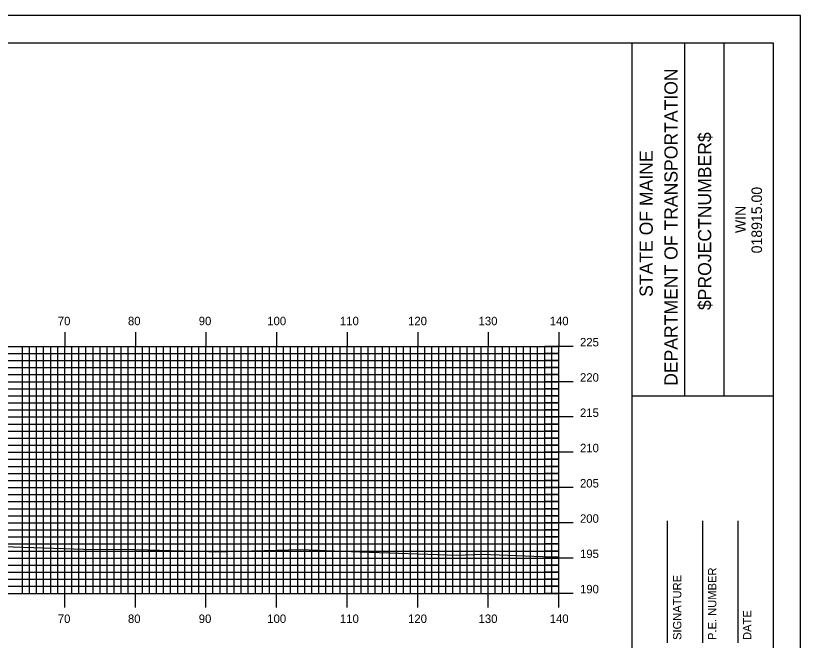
# Model space of a CAD drawing. Extents: x 1811374 to 1811717, y 442591 to 442811.
# Drawn here: x 1811602.4 to 1811713.6, y 442722 to 442810.5 of the extents above; entities that cross this region are included whole.
import ezdxf

# ---------------------------------------------------------------- set-up
doc = ezdxf.new("R2010")
doc.units = 0
for name, color, linetype in [('BORDER', 7, 'Continuous'), ('H_V ANNOTATION', 7, 'Continuous'), ('MAJOR', 7, 'Continuous'), ('MINOR', 7, 'Continuous'), ('PLOT BOUNDARY', 7, 'Continuous'), ('S_Roadway_Centerline', 7, 'Continuous')]:
    doc.layers.add(name, color=color, linetype=linetype)

msp = doc.modelspace()

# ---------------------------------------------------------------- linework, layer by layer
at = {"layer": 'BORDER'}
for p, q in [((1811689.8, 442596.67), (1811689.8, 442806.67)), ((1811697.26, 442756.66), (1811697.26, 442806.66)), ((1811702.85, 442756.66), (1811702.85, 442806.66)), ((1811689.8, 442756.65), (1811709.8, 442756.65)), ((1811694.8, 442721.67), (1811694.8, 442738.97)), ((1811699.8, 442721.67), (1811699.8, 442738.97)), ((1811704.8, 442721.67), (1811704.8, 442738.97))]:
    msp.add_line(p, q, dxfattribs=at)
msp.add_lwpolyline([(1811389.8, 442596.67), (1811709.8, 442596.67), (1811709.8, 442806.67), (1811389.8, 442806.67)], close=True, dxfattribs=at)
at = {"layer": 'MAJOR'}
for p, q in [((1811609.4, 442765.67), (1811609.4, 442763.67)), ((1811619.4, 442765.67), (1811619.4, 442763.67)), ((1811629.4, 442765.67), (1811629.4, 442763.67)), ((1811639.4, 442765.67), (1811639.4, 442763.67)), ((1811649.4, 442765.67), (1811649.4, 442763.67)), ((1811659.4, 442765.67), (1811659.4, 442763.67)), ((1811669.4, 442765.67), (1811669.4, 442763.67)), ((1811679.4, 442765.67), (1811679.4, 442763.67)), ((1811399.4, 442763.67), (1811679.4, 442763.67)), ((1811399.4, 442763.67), (1811679.4, 442763.67)), ((1811609.4, 442728.67), (1811609.4, 442763.67)), ((1811619.4, 442728.67), (1811619.4, 442763.67)), ((1811629.4, 442728.67), (1811629.4, 442763.67)), ((1811639.4, 442728.67), (1811639.4, 442763.67)), ((1811649.4, 442728.67), (1811649.4, 442763.67)), ((1811659.4, 442728.67), (1811659.4, 442763.67)), ((1811669.4, 442728.67), (1811669.4, 442763.67)), ((1811681.41, 442763.67), (1811677.4, 442763.67)), ((1811679.4, 442728.67), (1811679.4, 442763.67)), ((1811679.4, 442728.67), (1811679.4, 442763.67)), ((1811399.4, 442758.67), (1811679.4, 442758.67)), ((1811681.41, 442758.67), (1811677.4, 442758.67)), ((1811399.4, 442753.67), (1811679.4, 442753.67)), ((1811681.41, 442753.67), (1811677.4, 442753.67)), ((1811399.4, 442748.67), (1811679.4, 442748.67)), ((1811681.41, 442748.67), (1811677.4, 442748.67)), ((1811399.4, 442743.67), (1811679.4, 442743.67)), ((1811681.41, 442743.67), (1811677.4, 442743.67)), ((1811399.4, 442738.67), (1811679.4, 442738.67)), ((1811681.41, 442738.67), (1811677.4, 442738.67)), ((1811399.4, 442733.67), (1811679.4, 442733.67)), ((1811681.41, 442733.67), (1811677.4, 442733.67)), ((1811399.4, 442728.67), (1811679.4, 442728.67)), ((1811399.4, 442728.67), (1811679.4, 442728.67)), ((1811609.4, 442726.66), (1811609.4, 442728.67)), ((1811619.4, 442726.66), (1811619.4, 442728.67)), ((1811629.4, 442726.66), (1811629.4, 442728.67)), ((1811639.4, 442726.66), (1811639.4, 442728.67)), ((1811649.4, 442726.66), (1811649.4, 442728.67)), ((1811659.4, 442726.66), (1811659.4, 442728.67)), ((1811669.4, 442726.66), (1811669.4, 442728.67)), ((1811681.41, 442728.67), (1811677.4, 442728.67)), ((1811679.4, 442726.66), (1811679.4, 442728.67))]:
    msp.add_line(p, q, dxfattribs=at)
at = {"layer": 'MINOR'}
for p, q in [((1811603.4, 442728.67), (1811603.4, 442763.67)), ((1811604.4, 442728.67), (1811604.4, 442763.67)), ((1811605.4, 442728.67), (1811605.4, 442763.67)), ((1811606.4, 442728.67), (1811606.4, 442763.67)), ((1811607.4, 442728.67), (1811607.4, 442763.67)), ((1811608.4, 442728.67), (1811608.4, 442763.67)), ((1811610.4, 442728.67), (1811610.4, 442763.67)), ((1811611.4, 442728.67), (1811611.4, 442763.67)), ((1811612.4, 442728.67), (1811612.4, 442763.67)), ((1811613.4, 442728.67), (1811613.4, 442763.67)), ((1811614.4, 442728.67), (1811614.4, 442763.67)), ((1811615.4, 442728.67), (1811615.4, 442763.67)), ((1811616.4, 442728.67), (1811616.4, 442763.67)), ((1811617.4, 442728.67), (1811617.4, 442763.67)), ((1811618.4, 442728.67), (1811618.4, 442763.67)), ((1811620.4, 442728.67), (1811620.4, 442763.67)), ((1811621.4, 442728.67), (1811621.4, 442763.67)), ((1811622.4, 442728.67), (1811622.4, 442763.67)), ((1811623.4, 442728.67), (1811623.4, 442763.67)), ((1811624.4, 442728.67), (1811624.4, 442763.67)), ((1811625.4, 442728.67), (1811625.4, 442763.67)), ((1811626.4, 442728.67), (1811626.4, 442763.67)), ((1811627.4, 442728.67), (1811627.4, 442763.67)), ((1811628.4, 442728.67), (1811628.4, 442763.67)), ((1811630.4, 442728.67), (1811630.4, 442763.67)), ((1811631.4, 442728.67), (1811631.4, 442763.67)), ((1811632.4, 442728.67), (1811632.4, 442763.67)), ((1811633.4, 442728.67), (1811633.4, 442763.67)), ((1811634.4, 442728.67), (1811634.4, 442763.67)), ((1811635.4, 442728.67), (1811635.4, 442763.67)), ((1811636.4, 442728.67), (1811636.4, 442763.67)), ((1811637.4, 442728.67), (1811637.4, 442763.67)), ((1811638.4, 442728.67), (1811638.4, 442763.67)), ((1811640.4, 442728.67), (1811640.4, 442763.67)), ((1811641.4, 442728.67), (1811641.4, 442763.67)), ((1811642.4, 442728.67), (1811642.4, 442763.67)), ((1811643.4, 442728.67), (1811643.4, 442763.67)), ((1811644.4, 442728.67), (1811644.4, 442763.67)), ((1811645.4, 442728.67), (1811645.4, 442763.67)), ((1811646.4, 442728.67), (1811646.4, 442763.67)), ((1811647.4, 442728.67), (1811647.4, 442763.67)), ((1811648.4, 442728.67), (1811648.4, 442763.67)), ((1811650.4, 442728.67), (1811650.4, 442763.67)), ((1811651.4, 442728.67), (1811651.4, 442763.67)), ((1811652.4, 442728.67), (1811652.4, 442763.67)), ((1811653.4, 442728.67), (1811653.4, 442763.67)), ((1811654.4, 442728.67), (1811654.4, 442763.67)), ((1811655.4, 442728.67), (1811655.4, 442763.67)), ((1811656.4, 442728.67), (1811656.4, 442763.67)), ((1811657.4, 442728.67), (1811657.4, 442763.67)), ((1811658.4, 442728.67), (1811658.4, 442763.67)), ((1811660.4, 442728.67), (1811660.4, 442763.67)), ((1811661.4, 442728.67), (1811661.4, 442763.67)), ((1811662.4, 442728.67), (1811662.4, 442763.67)), ((1811663.4, 442728.67), (1811663.4, 442763.67)), ((1811664.4, 442728.67), (1811664.4, 442763.67)), ((1811665.4, 442728.67), (1811665.4, 442763.67)), ((1811666.4, 442728.67), (1811666.4, 442763.67)), ((1811667.4, 442728.67), (1811667.4, 442763.67)), ((1811668.4, 442728.67), (1811668.4, 442763.67)), ((1811670.4, 442728.67), (1811670.4, 442763.67)), ((1811671.4, 442728.67), (1811671.4, 442763.67)), ((1811672.4, 442728.67), (1811672.4, 442763.67)), ((1811673.4, 442728.67), (1811673.4, 442763.67)), ((1811674.4, 442728.67), (1811674.4, 442763.67)), ((1811675.4, 442728.67), (1811675.4, 442763.67)), ((1811676.4, 442728.67), (1811676.4, 442763.67)), ((1811677.4, 442728.67), (1811677.4, 442763.67)), ((1811678.4, 442728.67), (1811678.4, 442763.67)), ((1811399.4, 442762.67), (1811679.4, 442762.67)), ((1811679.4, 442762.67), (1811677.4, 442762.67)), ((1811399.4, 442761.67), (1811679.4, 442761.67)), ((1811679.4, 442761.67), (1811677.4, 442761.67)), ((1811399.4, 442760.67), (1811679.4, 442760.67)), ((1811679.4, 442760.67), (1811677.4, 442760.67)), ((1811399.4, 442759.67), (1811679.4, 442759.67)), ((1811679.4, 442759.67), (1811677.4, 442759.67)), ((1811399.4, 442757.67), (1811679.4, 442757.67)), ((1811679.4, 442757.67), (1811677.4, 442757.67)), ((1811399.4, 442756.67), (1811679.4, 442756.67)), ((1811679.4, 442756.67), (1811677.4, 442756.67)), ((1811399.4, 442755.67), (1811679.4, 442755.67)), ((1811679.4, 442755.67), (1811677.4, 442755.67)), ((1811399.4, 442754.67), (1811679.4, 442754.67)), ((1811679.4, 442754.67), (1811677.4, 442754.67)), ((1811399.4, 442752.67), (1811679.4, 442752.67)), ((1811679.4, 442752.67), (1811677.4, 442752.67)), ((1811399.4, 442751.67), (1811679.4, 442751.67)), ((1811679.4, 442751.67), (1811677.4, 442751.67)), ((1811399.4, 442750.67), (1811679.4, 442750.67)), ((1811679.4, 442750.67), (1811677.4, 442750.67)), ((1811399.4, 442749.67), (1811679.4, 442749.67)), ((1811679.4, 442749.67), (1811677.4, 442749.67)), ((1811399.4, 442747.67), (1811679.4, 442747.67)), ((1811679.4, 442747.67), (1811677.4, 442747.67)), ((1811399.4, 442746.67), (1811679.4, 442746.67)), ((1811679.4, 442746.67), (1811677.4, 442746.67)), ((1811399.4, 442745.67), (1811679.4, 442745.67)), ((1811679.4, 442745.67), (1811677.4, 442745.67)), ((1811399.4, 442744.67), (1811679.4, 442744.67)), ((1811679.4, 442744.67), (1811677.4, 442744.67)), ((1811399.4, 442742.67), (1811679.4, 442742.67)), ((1811679.4, 442742.67), (1811677.4, 442742.67)), ((1811399.4, 442741.67), (1811679.4, 442741.67)), ((1811679.4, 442741.67), (1811677.4, 442741.67)), ((1811399.4, 442740.67), (1811679.4, 442740.67)), ((1811679.4, 442740.67), (1811677.4, 442740.67)), ((1811399.4, 442739.67), (1811679.4, 442739.67)), ((1811679.4, 442739.67), (1811677.4, 442739.67)), ((1811399.4, 442737.67), (1811679.4, 442737.67)), ((1811679.4, 442737.67), (1811677.4, 442737.67)), ((1811399.4, 442736.67), (1811679.4, 442736.67)), ((1811679.4, 442736.67), (1811677.4, 442736.67)), ((1811399.4, 442735.67), (1811679.4, 442735.67)), ((1811679.4, 442735.67), (1811677.4, 442735.67)), ((1811399.4, 442734.67), (1811679.4, 442734.67)), ((1811679.4, 442734.67), (1811677.4, 442734.67)), ((1811399.4, 442732.67), (1811679.4, 442732.67)), ((1811679.4, 442732.67), (1811677.4, 442732.67)), ((1811399.4, 442731.67), (1811679.4, 442731.67)), ((1811679.4, 442731.67), (1811677.4, 442731.67)), ((1811399.4, 442730.67), (1811679.4, 442730.67)), ((1811679.4, 442730.67), (1811677.4, 442730.67)), ((1811399.4, 442729.67), (1811679.4, 442729.67)), ((1811679.4, 442729.67), (1811677.4, 442729.67))]:
    msp.add_line(p, q, dxfattribs=at)
at = {"layer": 'PLOT BOUNDARY'}
msp.add_lwpolyline([(1811373.62, 442590.55), (1811713.62, 442590.55), (1811713.62, 442810.55), (1811373.62, 442810.55)], close=True, dxfattribs=at)
at = {"layer": 'S_Roadway_Centerline'}
msp.add_lwpolyline([(1811593.54, 442735.54), (1811613.48, 442734.89), (1811617.83, 442734.95), (1811627.83, 442734.63), (1811629.75, 442734.58), (1811630.71, 442734.57), (1811642.84, 442734.89), (1811651.21, 442734.53), (1811664.94, 442734.1), (1811668.47, 442734.2), (1811677.1, 442733.9), (1811679.4, 442733.83)], dxfattribs=at)

# ---------------------------------------------------------------- texts
at = {"layer": 'BORDER'}
for s, height, p in [('DEPARTMENT OF TRANSPORTATION', 1.8635, (1811696.22, 442758.08)), ('$PROJECTNUMBER$', 1.8635, (1811700.99, 442768.82)), ('STATE OF MAINE', 1.8635, (1811692.71, 442770.69)), ('018915.00', 1.491, (1811708.19, 442776.86)), ('WIN', 1.491, (1811705.88, 442779.73)), ('P.E. NUMBER', 1.1811, (1811701.72, 442722.06)), ('SIGNATURE', 1.181, (1811696.76, 442722.06)), ('DATE', 1.181, (1811706.68, 442722.06))]:
    msp.add_text(s, height=height, rotation=90, dxfattribs=at).set_placement(p)
at = {"layer": 'H_V ANNOTATION'}
for s, p in [('70', (1811608.41, 442766.67)), ('80', (1811618.35, 442766.67)), ('90', (1811628.38, 442766.67)), ('100', (1811638.09, 442766.67)), ('110', (1811648.39, 442766.67)), ('120', (1811658.04, 442766.67)), ('130', (1811668.03, 442766.67)), ('140', (1811678.11, 442766.67)), ('225', (1811682.4, 442763.67)), ('220', (1811682.4, 442758.67)), ('215', (1811682.4, 442753.67)), ('210', (1811682.4, 442748.67)), ('205', (1811682.4, 442743.67)), ('200', (1811682.4, 442738.67)), ('195', (1811682.4, 442733.67)), ('190', (1811682.4, 442728.67)), ('70', (1811608.41, 442724.47)), ('80', (1811618.35, 442724.47)), ('90', (1811628.38, 442724.47)), ('100', (1811638.09, 442724.47)), ('110', (1811648.39, 442724.47)), ('120', (1811658.04, 442724.47)), ('130', (1811668.03, 442724.47)), ('140', (1811678.11, 442724.47))]:
    msp.add_text(s, height=1.2, dxfattribs=at).set_placement(p)

doc.saveas('drawing.dxf')
